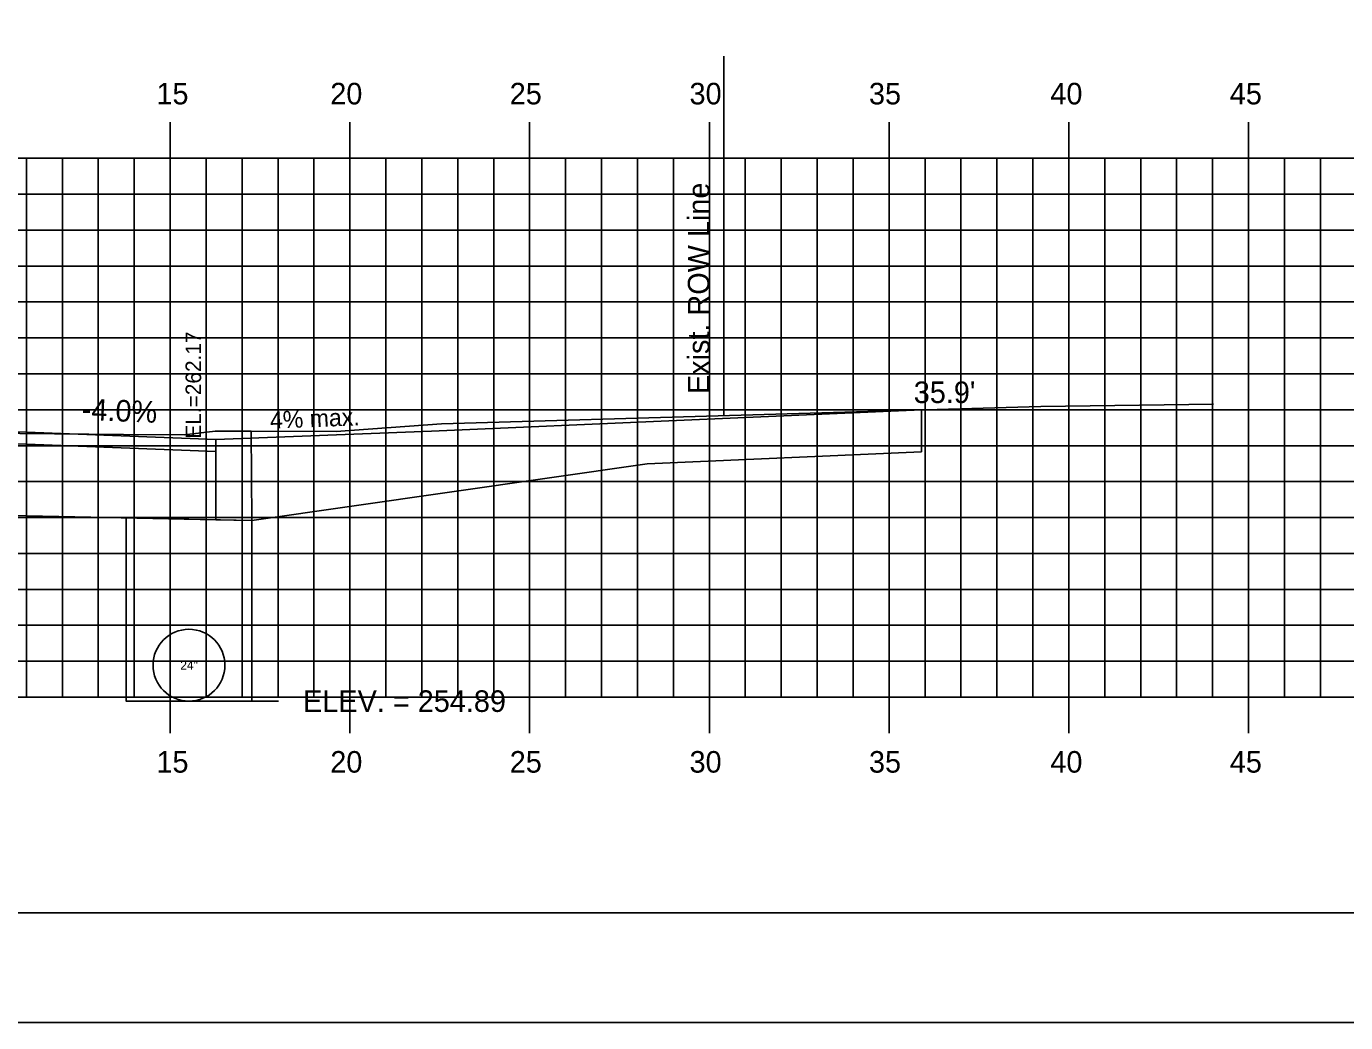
# Model space of a CAD drawing. Extents: x 856235 to 856405, y 366268 to 366378.
# Drawn here: x 856328.78 to 856365.48, y 366268.18 to 366295.91 of the extents above; entities that cross this region are included whole.
import ezdxf

# ---------------------------------------------------------------- set-up
doc = ezdxf.new("R2010")
doc.units = 0
for name, color, linetype in [('ANNOTATION', 7, 'Continuous'), ('BORDER', 7, 'Continuous'), ('D_Roadway_Drive_Gravel_RT', 7, 'Continuous'), ('D_Roadway_Drive_SubGrade', 7, 'Continuous'), ('D_Roadway_Edge_Shoulder', 7, 'Continuous'), ('D_Roadway_FinishedGrade', 7, 'Continuous'), ('D_Roadway_SubGrade', 7, 'Continuous'), ('D_Text_Standard', 7, 'Continuous'), ('E_ROW_Line', 7, 'Continuous'), ('H_V ANNOTATION', 7, 'Continuous'), ('JUNK COM EXC', 7, 'Continuous'), ('junk strct exc', 7, 'Continuous'), ('MAJOR', 7, 'Continuous'), ('MINOR', 7, 'Continuous'), ('PDRAIN', 7, 'Continuous'), ('PLOT BOUNDARY', 7, 'Continuous'), ('S_Roadway_Centerline', 7, 'Continuous')]:
    doc.layers.add(name, color=color, linetype=linetype)

msp = doc.modelspace()

# ---------------------------------------------------------------- linework, layer by layer
at = {"layer": 'BORDER'}
msp.add_line((856242.781, 366271.236), (856402.781, 366271.236), dxfattribs=at)
at = {"layer": 'D_Roadway_Drive_Gravel_RT'}
for p, q in [((856340.054, 366284.644), (856353.683, 366285.233)), ((856334.054, 366284.404), (856340.054, 366284.644)), ((856340.054, 366284.644), (856340.054, 366284.644))]:
    msp.add_line(p, q, dxfattribs=at)
at = {"layer": 'D_Roadway_Drive_SubGrade'}
for p, q in [((856353.683, 366285.233), (856353.683, 366284.067)), ((856335.054, 366282.155), (856346.054, 366283.735)), ((856334.054, 366282.175), (856335.054, 366282.155))]:
    msp.add_line(p, q, dxfattribs=at)
at = {"layer": 'D_Roadway_Edge_Shoulder'}
msp.add_line((856334.054, 366284.403), (856334.054, 366284.07), dxfattribs=at)
msp.add_lwpolyline([(856302.781, 366284.454), (856306.781, 366284.614), (856317.781, 366284.834), (856328.781, 366284.614), (856334.054, 366284.404)], dxfattribs=at)
at = {"layer": 'D_Roadway_FinishedGrade'}
msp.add_line((856346.054, 366283.735), (856353.683, 366284.065), dxfattribs=at)
at = {"layer": 'D_Roadway_SubGrade'}
msp.add_line((856334.054, 366284.07), (856334.054, 366282.175), dxfattribs=at)
msp.add_lwpolyline([(856306.781, 366282.281), (856306.781, 366284.281), (856317.781, 366284.501), (856328.781, 366284.281), (856328.781, 366282.281), (856317.781, 366282.501)], close=True, dxfattribs=at)
msp.add_lwpolyline([(856334.054, 366282.175), (856328.781, 366282.281), (856328.781, 366284.281), (856334.054, 366284.07)], dxfattribs=at)
at = {"layer": 'D_Text_Standard'}
msp.add_lwpolyline([(856335.054, 366277.126), (856335.119, 366277.126), (856335.799, 366277.126)], dxfattribs=at)
at = {"layer": 'E_ROW_Line'}
msp.add_line((856348.183, 366285.074), (856348.183, 366295.074), dxfattribs=at)
at = {"layer": 'JUNK COM EXC'}
msp.add_lwpolyline([(856291.781, 366283.178), (856301.781, 366282.181), (856306.781, 366282.281), (856317.781, 366282.501), (856328.781, 366282.281), (856335.054, 366282.155), (856335.038, 366284.636), (856334.033, 366284.637), (856333.255, 366284.546), (856333.193, 366284.537), (856331.485, 366284.547), (856328.602, 366284.573), (856324.051, 366284.665), (856317.749, 366284.776), (856313.162, 366284.614), (856307.467, 366284.395), (856303.535, 366284.254), (856301.781, 366284.168)], dxfattribs=at)
at = {"layer": 'junk strct exc'}
msp.add_lwpolyline([(856331.554, 366282.225), (856331.554, 366277.126), (856335.054, 366277.126), (856335.054, 366282.155)], close=True, dxfattribs=at)
at = {"layer": 'MAJOR'}
for p, q in [((856332.781, 366293.238), (856332.781, 366292.236)), ((856337.781, 366293.238), (856337.781, 366292.236)), ((856342.781, 366293.238), (856342.781, 366292.236)), ((856347.781, 366293.238), (856347.781, 366292.236)), ((856352.781, 366293.238), (856352.781, 366292.236)), ((856357.781, 366293.238), (856357.781, 366292.236)), ((856362.781, 366293.238), (856362.781, 366292.236)), ((856247.781, 366292.236), (856387.781, 366292.236)), ((856247.781, 366292.236), (856387.781, 366292.236)), ((856332.781, 366277.236), (856332.781, 366292.236)), ((856337.781, 366277.236), (856337.781, 366292.236)), ((856342.781, 366277.236), (856342.781, 366292.236)), ((856347.781, 366277.236), (856347.781, 366292.236)), ((856352.781, 366277.236), (856352.781, 366292.236)), ((856357.781, 366277.236), (856357.781, 366292.236)), ((856362.781, 366277.236), (856362.781, 366292.236)), ((856247.781, 366287.236), (856387.781, 366287.236)), ((856247.781, 366282.236), (856387.781, 366282.236)), ((856247.781, 366277.236), (856387.781, 366277.236)), ((856247.781, 366277.236), (856387.781, 366277.236)), ((856332.781, 366276.234), (856332.781, 366277.236)), ((856337.781, 366276.234), (856337.781, 366277.236)), ((856342.781, 366276.234), (856342.781, 366277.236)), ((856347.781, 366276.234), (856347.781, 366277.236)), ((856352.781, 366276.234), (856352.781, 366277.236)), ((856357.781, 366276.234), (856357.781, 366277.236)), ((856362.781, 366276.234), (856362.781, 366277.236))]:
    msp.add_line(p, q, dxfattribs=at)
at = {"layer": 'MINOR'}
for p, q in [((856328.781, 366277.236), (856328.781, 366292.236)), ((856329.781, 366277.236), (856329.781, 366292.236)), ((856330.781, 366277.236), (856330.781, 366292.236)), ((856331.781, 366277.236), (856331.781, 366292.236)), ((856333.781, 366277.236), (856333.781, 366292.236)), ((856334.781, 366277.236), (856334.781, 366292.236)), ((856335.781, 366277.236), (856335.781, 366292.236)), ((856336.781, 366277.236), (856336.781, 366292.236)), ((856338.781, 366277.236), (856338.781, 366292.236)), ((856339.781, 366277.236), (856339.781, 366292.236)), ((856340.781, 366277.236), (856340.781, 366292.236)), ((856341.781, 366277.236), (856341.781, 366292.236)), ((856343.781, 366277.236), (856343.781, 366292.236)), ((856344.781, 366277.236), (856344.781, 366292.236)), ((856345.781, 366277.236), (856345.781, 366292.236)), ((856346.781, 366277.236), (856346.781, 366292.236)), ((856348.781, 366277.236), (856348.781, 366292.236)), ((856349.781, 366277.236), (856349.781, 366292.236)), ((856350.781, 366277.236), (856350.781, 366292.236)), ((856351.781, 366277.236), (856351.781, 366292.236)), ((856353.781, 366277.236), (856353.781, 366292.236)), ((856354.781, 366277.236), (856354.781, 366292.236)), ((856355.781, 366277.236), (856355.781, 366292.236)), ((856356.781, 366277.236), (856356.781, 366292.236)), ((856358.781, 366277.236), (856358.781, 366292.236)), ((856359.781, 366277.236), (856359.781, 366292.236)), ((856360.781, 366277.236), (856360.781, 366292.236)), ((856361.781, 366277.236), (856361.781, 366292.236)), ((856363.781, 366277.236), (856363.781, 366292.236)), ((856364.781, 366277.236), (856364.781, 366292.236)), ((856247.781, 366291.236), (856387.781, 366291.236)), ((856247.781, 366290.236), (856387.781, 366290.236)), ((856247.781, 366289.236), (856387.781, 366289.236)), ((856247.781, 366288.236), (856387.781, 366288.236)), ((856247.781, 366286.236), (856387.781, 366286.236)), ((856247.781, 366285.236), (856387.781, 366285.236)), ((856247.781, 366284.236), (856387.781, 366284.236)), ((856247.781, 366283.236), (856387.781, 366283.236)), ((856247.781, 366281.236), (856387.781, 366281.236)), ((856247.781, 366280.236), (856387.781, 366280.236)), ((856247.781, 366279.236), (856387.781, 366279.236)), ((856247.781, 366278.236), (856387.781, 366278.236))]:
    msp.add_line(p, q, dxfattribs=at)
at = {"layer": 'PDRAIN'}
msp.add_lwpolyline([(856331.554, 366282.225), (856331.554, 366277.126), (856335.054, 366277.126), (856335.054, 366282.155)], dxfattribs=at)
msp.add_circle((856333.304, 366278.126), 1, dxfattribs=at)
at = {"layer": 'PLOT BOUNDARY'}
msp.add_lwpolyline([(856234.688, 366268.177), (856404.688, 366268.177), (856404.688, 366378.177), (856234.688, 366378.177)], close=True, dxfattribs=at)
at = {"layer": 'S_Roadway_Centerline'}
msp.add_lwpolyline([(856291.653, 366283.81), (856293.851, 366284.031), (856296.799, 366284.263), (856298.619, 366284.286), (856300.35, 366284.265), (856300.663, 366284.113), (856300.753, 366284.127), (856300.892, 366284.124), (856303.535, 366284.254), (856307.467, 366284.395), (856313.162, 366284.614), (856317.749, 366284.776), (856324.051, 366284.665), (856328.602, 366284.573), (856331.485, 366284.547), (856333.193, 366284.537), (856333.255, 366284.546), (856334.033, 366284.637), (856337.4, 366284.635), (856340.331, 366284.846), (856357.003, 366285.329), (856361.802, 366285.388)], dxfattribs=at)

# ---------------------------------------------------------------- texts
at = {"layer": 'ANNOTATION'}
msp.add_text('-4.0%', height=0.6, rotation=357.7085, dxfattribs=at).set_placement((856330.313, 366284.954))
at = {"layer": 'D_Roadway_Drive_Gravel_RT'}
msp.add_text('4% max.', height=0.48, rotation=2.2906, dxfattribs=at).set_placement((856335.566, 366284.705))
at = {"layer": 'D_Text_Standard'}
msp.add_text(' EL.=262.17', height=0.4335, rotation=90, dxfattribs=at).set_placement((856333.642, 366284.272))
for s, p in [("35.9'", (856353.467, 366285.423)), ('ELEV. = 254.89', (856336.479, 366276.826))]:
    msp.add_text(s, height=0.6, dxfattribs=at).set_placement(p)
at = {"layer": 'E_ROW_Line'}
msp.add_text('Exist. ROW Line', height=0.6, rotation=90, dxfattribs=at).set_placement((856347.782, 366285.674))
at = {"layer": 'H_V ANNOTATION'}
for s, p in [('15', (856332.398, 366293.736)), ('20', (856337.235, 366293.736)), ('25', (856342.227, 366293.736)), ('30', (856347.229, 366293.736)), ('35', (856352.221, 366293.736)), ('40', (856357.267, 366293.736)), ('45', (856362.259, 366293.736)), ('15', (856332.398, 366275.136)), ('20', (856337.235, 366275.136)), ('25', (856342.227, 366275.136)), ('30', (856347.229, 366275.136)), ('35', (856352.221, 366275.136)), ('40', (856357.267, 366275.136)), ('45', (856362.259, 366275.136))]:
    msp.add_text(s, height=0.6, dxfattribs=at).set_placement(p)
at = {"layer": 'PDRAIN'}
msp.add_text('24"', height=0.25, dxfattribs=at).set_placement((856333.062, 366278.001))

doc.saveas('drawing.dxf')
